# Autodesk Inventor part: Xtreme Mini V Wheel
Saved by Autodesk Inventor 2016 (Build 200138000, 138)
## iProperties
Created: 2016-03
Part Number: Xtreme Mini V Wheel
Material: Generic
Document SubType Name: Modeling
Designer: bongo_000
Density: 1 g/cm^3
Appearance: Default
Author: bongo_000
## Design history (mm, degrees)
feature "REVOLVE1"
body "Solid1"
